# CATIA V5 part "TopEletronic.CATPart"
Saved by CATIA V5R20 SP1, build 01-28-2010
Part number: TopEletronic
Bounding box of the stored display mesh (mm): x 0 to 180, y 0 to 130, z 0 to 2
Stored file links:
  C:\Users\elisf\Desktop\Elis\ENSINOFATEC\MAV5\DIP\Labirinto\RealBox\TopEletronic.CATPart
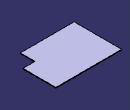
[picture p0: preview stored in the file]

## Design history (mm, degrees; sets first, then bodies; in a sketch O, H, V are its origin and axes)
Body1 (main body)
  Sketch1 on xy-plane, origin (0, 0, 0), H (1, 0, 0), V (0, 1, 0)
    line L1 (0, 0) -> (180, 0)
    line L2 (180, 0) -> (180, 130)
    line L3 (180, 130) -> (0, 130)
    line L4 (0, 130) -> (0, 0)
    length L4 = 130
    length L1 = 180
    horizontal: L1 H, L3 H
    vertical: L2 V, L4 V
  Pad1: profile Sketch1, direction (0, 0, 1), length 2
  Sketch2 on end face of Pad1, origin (0, 0, 2), H (1, 0, 0), V (0, 1, 0)
    line L1 (180, 0) -> (147, 0)
    line L2 (147, 0) -> (147, 40)
    line L3 (147, 40) -> (180, 40)
    line L4 (180, 40) -> (180, 0)
    length L4 = 40
    length L1 = 33
    horizontal: L1 H, L3 H
    vertical: L2 V, L4 V
  Pocket1: profile Sketch2, direction (0, 0, -1), length 3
